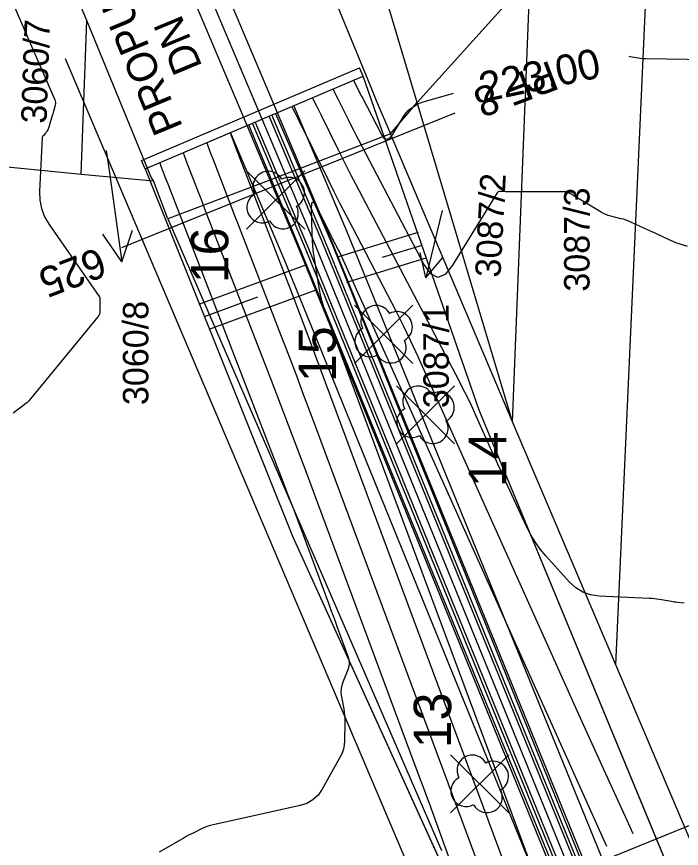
# Model space of a CAD drawing. Extents: x -534410 to -534262, y -1190162 to -1189584.
# Drawn here: x -534356.09 to -534333.9, y -1189974.68 to -1189946.91 of the extents above; entities that cross this region are included whole.
import ezdxf

# ---------------------------------------------------------------- set-up
doc = ezdxf.new("R2010")
doc.units = 0
for name, color, linetype in [('30', 7, 'Continuous'), ('31', 7, 'Continuous'), ('40', 7, 'Continuous'), ('_linie', 7, 'Continuous'), ('_N_osa', 7, 'Continuous'), ('_N_tenká', 7, 'Continuous'), ('_N_tenká_velmi', 7, 'Continuous'), ('_N_text', 7, 'Continuous'), ('_přístup', 7, 'Continuous'), ('_tenka', 7, 'Continuous'), ('_tenká_čárkovaná', 7, 'Continuous'), ('_velmi_tenka', 7, 'Continuous'), ('Default', 7, 'Continuous'), ('Hranice parcel', 7, 'Continuous'), ('Parcelní čísla', 7, 'Continuous'), ('Pop  PČ popisy', 7, 'Continuous'), ('Vnitřní kresba', 7, 'Continuous')]:
    doc.layers.add(name, color=color, linetype=linetype)

msp = doc.modelspace()

# ---------------------------------------------------------------- linework, layer by layer
at = {"layer": '30'}
for points in [[(-534332.347, -1189948.361), (-534335.078, -1189948.316), (-534335.145, -1189948.314), (-534335.212, -1189948.309), (-534335.279, -1189948.301), (-534335.345, -1189948.291), (-534335.61, -1189948.245), (-534335.641, -1189948.24)], [(-534341.513, -1189949.473), (-534342.557, -1189949.771), (-534342.618, -1189949.791), (-534342.676, -1189949.816), (-534342.731, -1189949.846), (-534342.785, -1189949.88), (-534342.994, -1189950.027), (-534343.044, -1189950.066), (-534343.09, -1189950.11), (-534343.13, -1189950.158), (-534343.166, -1189950.21), (-534343.579, -1189950.88), (-534343.658, -1189950.977), (-534343.735, -1189951.007), (-534343.809, -1189950.971), (-534343.881, -1189950.87), (-534344.566, -1189949.564), (-534344.594, -1189949.511), (-534344.622, -1189949.457), (-534344.649, -1189949.403), (-534344.676, -1189949.349), (-534344.783, -1189949.133), (-534344.81, -1189949.079), (-534344.837, -1189949.025), (-534344.837, -1189949.025)], [(-534333.806, -1189966.483), (-534334.037, -1189966.462), (-534334.086, -1189966.456), (-534334.135, -1189966.45), (-534334.184, -1189966.443), (-534334.232, -1189966.436), (-534334.633, -1189966.367), (-534334.717, -1189966.354), (-534334.8, -1189966.343), (-534334.884, -1189966.336), (-534334.968, -1189966.33), (-534336.643, -1189966.251), (-534336.926, -1189966.212), (-534337.185, -1189966.121), (-534337.42, -1189965.978), (-534337.63, -1189965.784), (-534338.423, -1189964.906), (-534338.612, -1189964.681), (-534338.782, -1189964.443), (-534338.934, -1189964.193), (-534339.067, -1189963.93), (-534339.767, -1189962.411), (-534339.896, -1189962.131), (-534340.023, -1189961.852), (-534340.15, -1189961.572), (-534340.277, -1189961.292), (-534340.781, -1189960.17), (-534340.909, -1189959.891), (-534341.041, -1189959.614), (-534341.178, -1189959.338), (-534341.318, -1189959.065), (-534344.768, -1189952.496), (-534344.917, -1189952.21), (-534345.064, -1189951.923), (-534345.21, -1189951.635), (-534345.354, -1189951.346), (-534345.926, -1189950.189), (-534346.069, -1189949.9), (-534346.214, -1189949.612), (-534346.214, -1189949.611)], [(-534349.741, -1189951.113), (-534349.741, -1189951.114), (-534349.634, -1189951.413), (-534349.521, -1189951.711), (-534349.063, -1189952.897), (-534348.948, -1189953.194), (-534348.834, -1189953.49), (-534348.719, -1189953.787), (-534348.604, -1189954.084), (-534347.276, -1189957.52), (-534347.018, -1189958.192), (-534346.762, -1189958.865), (-534346.507, -1189959.539), (-534346.256, -1189960.213), (-534339.969, -1189977.123)], [(-534351.313, -1189951.783), (-534351.313, -1189951.783), (-534351.287, -1189951.853), (-534351.261, -1189951.924), (-534351.125, -1189952.275), (-534351.044, -1189952.485), (-534347.202, -1189962.427), (-534347.031, -1189962.871), (-534346.862, -1189963.316), (-534346.693, -1189963.762), (-534346.527, -1189964.208), (-534345.681, -1189966.484), (-534345.606, -1189966.685), (-534345.532, -1189966.887), (-534345.458, -1189967.088), (-534345.385, -1189967.29), (-534345.025, -1189968.289), (-534344.996, -1189968.395), (-534344.988, -1189968.501), (-534345, -1189968.606), (-534345.033, -1189968.711), (-534345.203, -1189969.129), (-534345.238, -1189969.235), (-534345.257, -1189969.342), (-534345.261, -1189969.45), (-534345.25, -1189969.561), (-534345.171, -1189970.016), (-534345.154, -1189970.129), (-534345.142, -1189970.243), (-534345.136, -1189970.357), (-534345.135, -1189970.472), (-534345.143, -1189971.09), (-534345.154, -1189971.229), (-534345.181, -1189971.363), (-534345.225, -1189971.493), (-534345.285, -1189971.619), (-534345.888, -1189972.697), (-534346.027, -1189972.897), (-534346.197, -1189973.056), (-534346.398, -1189973.173), (-534346.629, -1189973.249), (-534349.578, -1189973.903), (-534349.66, -1189973.924), (-534349.74, -1189973.949), (-534349.818, -1189973.979), (-534349.895, -1189974.014), (-534350.199, -1189974.162), (-534350.275, -1189974.2), (-534350.35, -1189974.239), (-534350.424, -1189974.28), (-534350.497, -1189974.321), (-534351.326, -1189974.802)], [(-534333.937, -1189988.624), (-534345.745, -1189956.862), (-534345.821, -1189956.641), (-534345.887, -1189956.416), (-534345.941, -1189956.189), (-534345.984, -1189955.959), (-534346.144, -1189954.985), (-534346.174, -1189954.777), (-534346.198, -1189954.569), (-534346.214, -1189954.36), (-534346.223, -1189954.15), (-534346.245, -1189953.308), (-534346.238, -1189953.148), (-534346.207, -1189953.088), (-534346.151, -1189953.127), (-534346.07, -1189953.265), (-534345.568, -1189954.282), (-534345.54, -1189954.337), (-534345.513, -1189954.392), (-534345.485, -1189954.446), (-534345.456, -1189954.501), (-534345.342, -1189954.718), (-534345.314, -1189954.773), (-534345.287, -1189954.828), (-534345.26, -1189954.883), (-534345.235, -1189954.939), (-534336.4, -1189974.599)]]:
    msp.add_lwpolyline(points, dxfattribs=at)
at = {"layer": '31'}
for points in [[(-534356.958, -1189944.756), (-534354.814, -1189949.683), (-534354.799, -1189949.726), (-534354.792, -1189949.769), (-534354.792, -1189949.813), (-534354.8, -1189949.858), (-534354.858, -1189950.072), (-534354.865, -1189950.099), (-534354.873, -1189950.126), (-534354.881, -1189950.153), (-534354.889, -1189950.18), (-534354.922, -1189950.287), (-534354.931, -1189950.314), (-534354.939, -1189950.341), (-534354.947, -1189950.368), (-534354.954, -1189950.395), (-534355.012, -1189950.595), (-534355.018, -1189950.613), (-534355.024, -1189950.631), (-534355.032, -1189950.648), (-534355.041, -1189950.665), (-534355.078, -1189950.732), (-534355.088, -1189950.748), (-534355.099, -1189950.763), (-534355.11, -1189950.778), (-534355.123, -1189950.793), (-534355.197, -1189950.871), (-534355.211, -1189950.889), (-534355.222, -1189950.91), (-534355.229, -1189950.931), (-534355.232, -1189950.955), (-534355.32, -1189952.734), (-534355.312, -1189953.032), (-534355.256, -1189953.316), (-534355.153, -1189953.587), (-534355.002, -1189953.844), (-534353.33, -1189956.253), (-534353.322, -1189956.267), (-534353.316, -1189956.281), (-534353.312, -1189956.297), (-534353.311, -1189956.313), (-534353.311, -1189956.736), (-534353.315, -1189956.789), (-534353.328, -1189956.838), (-534353.35, -1189956.885), (-534353.38, -1189956.928), (-534355.625, -1189959.662), (-534355.686, -1189959.732), (-534355.751, -1189959.797), (-534355.821, -1189959.858), (-534355.894, -1189959.915), (-534356.21, -1189960.143)], [(-534333.691, -1189954.585), (-534334.001, -1189954.482), (-534334.079, -1189954.455), (-534334.155, -1189954.426), (-534334.23, -1189954.394), (-534334.305, -1189954.361), (-534334.755, -1189954.146), (-534334.854, -1189954.1), (-534334.952, -1189954.054), (-534335.051, -1189954.008), (-534335.15, -1189953.963), (-534335.583, -1189953.764), (-534335.664, -1189953.73), (-534335.746, -1189953.699), (-534335.83, -1189953.673), (-534335.915, -1189953.651), (-534336.257, -1189953.57), (-534336.342, -1189953.547), (-534336.424, -1189953.517), (-534336.503, -1189953.481), (-534336.579, -1189953.438), (-534337.516, -1189952.864), (-534337.531, -1189952.854), (-534337.547, -1189952.845), (-534337.563, -1189952.836), (-534337.579, -1189952.828), (-534337.661, -1189952.787), (-534337.669, -1189952.782), (-534337.677, -1189952.779), (-534337.685, -1189952.775), (-534337.693, -1189952.771), (-534337.727, -1189952.756), (-534337.735, -1189952.753), (-534337.743, -1189952.751), (-534337.752, -1189952.75), (-534337.761, -1189952.75), (-534337.813, -1189952.751), (-534337.824, -1189952.751), (-534337.836, -1189952.752), (-534337.847, -1189952.752), (-534337.859, -1189952.752), (-534339.627, -1189952.752), (-534339.639, -1189952.752), (-534339.65, -1189952.752), (-534339.662, -1189952.752), (-534339.674, -1189952.753), (-534339.72, -1189952.754), (-534339.732, -1189952.754), (-534339.743, -1189952.754), (-534339.755, -1189952.754), (-534339.766, -1189952.753), (-534339.943, -1189952.739), (-534339.975, -1189952.74), (-534340.002, -1189952.749), (-534340.026, -1189952.766), (-534340.045, -1189952.791), (-534341.534, -1189955.206), (-534341.784, -1189955.513), (-534342.027, -1189955.61), (-534342.263, -1189955.496), (-534342.492, -1189955.173), (-534344.667, -1189951.03), (-534344.756, -1189950.86), (-534344.843, -1189950.69), (-534344.929, -1189950.519), (-534345.015, -1189950.348), (-534345.354, -1189949.661), (-534345.44, -1189949.489), (-534345.525, -1189949.318), (-534345.525, -1189949.318)], [(-534335.502, -1189974.194), (-534335.706, -1189973.75), (-534336.543, -1189971.917), (-534337.375, -1189970.082), (-534338.203, -1189968.246), (-534342.689, -1189958.264), (-534342.928, -1189957.743), (-534343.175, -1189957.226), (-534343.429, -1189956.713), (-534343.692, -1189956.203), (-534344.869, -1189953.962), (-534345.078, -1189953.56), (-534345.286, -1189953.156), (-534345.49, -1189952.751), (-534345.693, -1189952.345), (-534346.692, -1189950.323), (-534346.796, -1189950.113), (-534346.901, -1189949.904), (-534346.901, -1189949.904)], [(-534348.961, -1189950.781), (-534348.961, -1189950.781), (-534348.873, -1189951.024), (-534348.782, -1189951.265), (-534347.95, -1189953.419), (-534347.826, -1189953.741), (-534347.702, -1189954.063), (-534347.577, -1189954.385), (-534347.453, -1189954.707), (-534346.955, -1189955.994), (-534346.832, -1189956.316), (-534346.709, -1189956.639), (-534346.587, -1189956.961), (-534346.466, -1189957.285), (-534337.113, -1189982.443)], [(-534350.527, -1189951.448), (-534350.527, -1189951.448), (-534350.46, -1189951.633), (-534350.391, -1189951.817), (-534350.108, -1189952.551), (-534350.037, -1189952.734), (-534349.966, -1189952.918), (-534349.895, -1189953.101), (-534349.824, -1189953.285), (-534347.597, -1189959.046), (-534347.204, -1189960.069), (-534346.815, -1189961.092), (-534346.428, -1189962.116), (-534346.045, -1189963.142), (-534342.825, -1189971.804), (-534342.573, -1189972.484), (-534342.322, -1189973.165), (-534342.073, -1189973.847), (-534341.826, -1189974.529), (-534340.607, -1189977.906)]]:
    msp.add_lwpolyline(points, dxfattribs=at)
at = {"layer": '_linie'}
for points in [[(-534351.8, -1189951.99), (-534344.52, -1189948.89)], [(-534351.8, -1189951.99), (-534346.88, -1189964.25), (-534328.11, -1190005.55), (-534325.796, -1190021.686), (-534325.86, -1190050.97), (-534326.22, -1190078.56), (-534326.79, -1190120.4), (-534329.12, -1190134.93), (-534323.49, -1190133.89), (-534321.38, -1190121.46), (-534319.59, -1190053.22), (-534320.45, -1190021.195), (-534322.75, -1190003.33), (-534340.65, -1189960.04), (-534344.52, -1189948.89)], [(-534347.45, -1189950.137), (-534345.54, -1189954.54), (-534325.02, -1190005.35), (-534322.054, -1190021.393), (-534321.72, -1190051.56), (-534322.31, -1190078.15), (-534323.81, -1190120.37), (-534326.521, -1190134.45)], [(-534328.194, -1190134.759), (-534324.85, -1190120.45), (-534324.6, -1190078.17), (-534323.54, -1190051.92), (-534323.273, -1190021.516), (-534325.81, -1190005.43), (-534346.66, -1189954.59), (-534348.342, -1189950.518)]]:
    msp.add_lwpolyline(points, dxfattribs=at)
at = {"layer": '_N_osa'}
for points in [[(-534347.892, -1189950.326), (-534351.93, -1189940.77), (-534351.95, -1189940.722)], [(-534327.357, -1190134.604), (-534324.33, -1190120.41), (-534323.455, -1190078.16), (-534322.63, -1190051.74), (-534322.663, -1190021.455), (-534325.415, -1190005.39), (-534346.1, -1189954.565), (-534347.892, -1189950.326)]]:
    msp.add_lwpolyline(points, dxfattribs=at)
at = {"layer": '_N_tenká'}
for points in [[(-534326.133, -1190134.378), (-534323.183, -1190120.543), (-534322.305, -1190078.19), (-534321.48, -1190051.757), (-534321.513, -1190021.356), (-534324.303, -1190005.072), (-534345.038, -1189954.124), (-534346.832, -1189949.878)], [(-534328.581, -1190134.83), (-534325.477, -1190120.277), (-534324.605, -1190078.13), (-534323.78, -1190051.723), (-534323.813, -1190021.553), (-534326.527, -1190005.708), (-534347.162, -1189955.006), (-534348.951, -1189950.773)]]:
    msp.add_lwpolyline(points, dxfattribs=at)
at = {"layer": '_N_tenká_velmi'}
for points in [[(-534326.772, -1190134.496), (-534323.781, -1190120.474), (-534322.905, -1190078.174), (-534322.08, -1190051.748), (-534322.113, -1190021.407), (-534324.883, -1190005.238), (-534345.592, -1189954.354), (-534347.385, -1189950.112)], [(-534327.623, -1190134.654), (-534324.579, -1190120.381), (-534323.705, -1190078.154), (-534322.88, -1190051.736), (-534322.913, -1190021.476), (-534325.657, -1190005.459), (-534346.331, -1189954.661), (-534348.122, -1189950.423)], [(-534327.091, -1190134.555), (-534324.081, -1190120.439), (-534323.205, -1190078.166), (-534322.38, -1190051.744), (-534322.413, -1190021.433), (-534325.173, -1190005.321), (-534345.869, -1189954.469), (-534347.661, -1189950.228)], [(-534326.985, -1190134.536), (-534323.981, -1190120.45), (-534323.105, -1190078.169), (-534322.28, -1190051.745), (-534322.313, -1190021.425), (-534325.076, -1190005.293), (-534345.777, -1189954.431), (-534347.569, -1189950.189)], [(-534327.943, -1190134.713), (-534324.879, -1190120.346), (-534324.005, -1190078.146), (-534323.18, -1190051.732), (-534323.213, -1190021.502), (-534325.947, -1190005.542), (-534346.608, -1189954.776), (-534348.398, -1189950.54)], [(-534327.73, -1190134.673), (-534324.679, -1190120.37), (-534323.805, -1190078.151), (-534322.98, -1190051.735), (-534323.013, -1190021.485), (-534325.754, -1190005.487), (-534346.423, -1189954.699), (-534348.214, -1189950.462)]]:
    msp.add_lwpolyline(points, dxfattribs=at)
at = {"layer": '_N_text'}
for points in [[(-534341.462, -1189950.129), (-534352.588, -1189954.625)], [(-534332.014, -1189973.259), (-534343.129, -1189977.783)]]:
    msp.add_lwpolyline(points, dxfattribs=at)
at = {"layer": '_přístup'}
for p, q in [((-534346.467, -1189954.003), (-534348.413, -1189952.057)), ((-534348.413, -1189954.003), (-534346.467, -1189952.057)), ((-534342.867, -1189958.483), (-534344.813, -1189956.537)), ((-534344.813, -1189958.483), (-534342.867, -1189956.537)), ((-534341.467, -1189961.173), (-534343.413, -1189959.227)), ((-534343.413, -1189961.173), (-534341.467, -1189959.227)), ((-534339.658, -1189973.494), (-534341.604, -1189971.548)), ((-534341.604, -1189973.494), (-534339.658, -1189971.548))]:
    msp.add_line(p, q, dxfattribs=at)
msp.add_lwpolyline([(-534330.552, -1190135.191), (-534328.648, -1190119.819), (-534326.845, -1190024.247), (-534332.805, -1189999.297), (-534354.454, -1189948.317)], dxfattribs=at)
for centre in [(-534347.44, -1189953.03), (-534343.84, -1189957.51), (-534342.44, -1189960.2), (-534340.631, -1189972.521)]:
    msp.add_circle(centre, 0.000512, dxfattribs=at)
for centre, start, end in [((-534347.685, -1189952.581), 28.6209, 208.6209), ((-534346.991, -1189952.785), 298.6209, 118.6209), ((-534347.889, -1189953.275), 118.6209, 298.6209), ((-534347.195, -1189953.479), 208.6209, 28.6209), ((-534344.085, -1189957.061), 28.6209, 208.6209), ((-534343.391, -1189957.265), 298.6209, 118.6209), ((-534344.289, -1189957.755), 118.6209, 298.6209), ((-534343.595, -1189957.959), 208.6209, 28.6209), ((-534342.685, -1189959.751), 28.6209, 208.6209), ((-534341.991, -1189959.955), 298.6209, 118.6209), ((-534342.889, -1189960.445), 118.6209, 298.6209), ((-534342.195, -1189960.649), 208.6209, 28.6209), ((-534340.876, -1189972.072), 28.6209, 208.6209), ((-534340.182, -1189972.276), 298.6209, 118.6209), ((-534341.081, -1189972.766), 118.6209, 298.6209), ((-534340.386, -1189972.971), 208.6209, 28.6209)]:
    msp.add_arc(centre, 0.512, start, end, dxfattribs=at)
at = {"layer": '_tenka'}
for points in [[(-534351.8, -1189951.99), (-534344.52, -1189948.89)], [(-534351.8, -1189951.99), (-534344.52, -1189948.89)], [(-534351.8, -1189951.99), (-534346.88, -1189964.25), (-534328.11, -1190005.55), (-534325.796, -1190021.686), (-534325.86, -1190050.97), (-534326.22, -1190078.56), (-534326.79, -1190120.4), (-534329.12, -1190134.93), (-534323.49, -1190133.89), (-534321.38, -1190121.46), (-534319.59, -1190053.22), (-534320.45, -1190021.195), (-534322.75, -1190003.33), (-534340.65, -1189960.04), (-534344.52, -1189948.89)], [(-534351.8, -1189951.99), (-534344.52, -1189948.89)], [(-534327.55, -1190134.64), (-534323.49, -1190133.89), (-534321.38, -1190121.46), (-534319.59, -1190053.22), (-534320.45, -1190021.195), (-534322.75, -1190003.33), (-534340.65, -1189960.04), (-534344.52, -1189948.89)], [(-534347.45, -1189950.137), (-534345.54, -1189954.54), (-534325.02, -1190005.35), (-534322.054, -1190021.393), (-534321.72, -1190051.56), (-534322.31, -1190078.15), (-534323.81, -1190120.37), (-534326.521, -1190134.45)], [(-534347.45, -1189950.137), (-534345.54, -1189954.54), (-534325.02, -1190005.35), (-534322.054, -1190021.393), (-534321.72, -1190051.56), (-534322.31, -1190078.15), (-534323.81, -1190120.37), (-534326.521, -1190134.45)], [(-534328.194, -1190134.759), (-534324.85, -1190120.45), (-534324.6, -1190078.17), (-534323.54, -1190051.92), (-534323.273, -1190021.516), (-534325.81, -1190005.43), (-534346.66, -1189954.59), (-534348.342, -1189950.518)], [(-534328.194, -1190134.759), (-534324.85, -1190120.45), (-534324.6, -1190078.17), (-534323.54, -1190051.92), (-534323.273, -1190021.516), (-534325.81, -1190005.43), (-534346.66, -1189954.59), (-534348.342, -1189950.518)], [(-534351.8, -1189951.99), (-534346.88, -1189964.25), (-534328.11, -1190005.55), (-534325.796, -1190021.686), (-534325.86, -1190050.97), (-534326.22, -1190078.56), (-534326.79, -1190120.4), (-534329.12, -1190134.93), (-534327.55, -1190134.64)]]:
    msp.add_lwpolyline(points, dxfattribs=at)
at = {"layer": '_tenká_čárkovaná'}
for points in [[(-534347.385, -1189950.112), (-534351.423, -1189940.558), (-534351.442, -1189940.511)], [(-534348.398, -1189950.54), (-534352.437, -1189940.982), (-534352.458, -1189940.932)]]:
    msp.add_lwpolyline(points, dxfattribs=at)
at = {"layer": '_velmi_tenka'}
for p, q in [((-534342.69, -1189954.112), (-534345.342, -1189954.926)), ((-534342.558, -1189954.542), (-534343.884, -1189954.949)), ((-534342.426, -1189954.972), (-534345.078, -1189955.787)), ((-534349.977, -1189956.496), (-534346.397, -1189955.186)), ((-534349.822, -1189956.919), (-534348.032, -1189956.264)), ((-534349.667, -1189957.341), (-534346.087, -1189956.032))]:
    msp.add_line(p, q, dxfattribs=at)
at = {"layer": 'Default'}
for p, q in [((-534340.65, -1189960.04), (-534344.52, -1189948.89)), ((-534344.52, -1189948.89), (-534344.52, -1189948.89)), ((-534351.8, -1189951.99), (-534346.88, -1189964.25)), ((-534322.75, -1190003.33), (-534340.65, -1189960.04)), ((-534346.88, -1189964.25), (-534328.11, -1190005.55))]:
    msp.add_line(p, q, dxfattribs=at)
at = {"layer": 'Hranice parcel'}
for p, q in [((-534342.72, -1189949.77), (-534345.7, -1189939.75)), ((-534353.75, -1189947.04), (-534355.84, -1189941.94)), ((-534339.54, -1189960.43), (-534338.98, -1189946.42)), ((-534336.09, -1189968.55), (-534335.08, -1189946.31)), ((-534353.94, -1189952.16), (-534353.75, -1189947.04)), ((-534351.79, -1189951.81), (-534353.75, -1189947.04)), ((-534343.61, -1189950.82), (-534342.72, -1189949.77)), ((-534339.54, -1189960.43), (-534342.72, -1189949.77)), ((-534339.54, -1189960.43), (-534343.61, -1189950.82)), ((-534356.92, -1189951.87), (-534353.94, -1189952.16)), ((-534353.94, -1189952.16), (-534351.89, -1189952.35)), ((-534351.89, -1189952.35), (-534351.52, -1189952.39)), ((-534351.04, -1189953.66), (-534351.52, -1189952.39)), ((-534351.04, -1189953.66), (-534341.9, -1189974.75)), ((-534336.09, -1189968.55), (-534339.54, -1189960.43)), ((-534333.52, -1189974.6), (-534336.09, -1189968.55))]:
    msp.add_line(p, q, dxfattribs=at)
for points in [[(-534348.85, -1189938.1), (-534348.39, -1189939.21), (-534348.2, -1189939.68), (-534344.29, -1189949.21), (-534344.09, -1189949.7), (-534343.61, -1189950.82)], [(-534342.72, -1189949.77), (-534339.72, -1189946.46), (-534338.98, -1189946.42)], [(-534343.61, -1189950.82), (-534346.53, -1189951.94), (-534347.64, -1189952.36), (-534351.04, -1189953.66)], [(-534351.52, -1189952.39), (-534351.6, -1189952.27), (-534351.79, -1189951.81)]]:
    msp.add_lwpolyline(points, dxfattribs=at)
at = {"layer": 'Pop  PČ popisy'}
for p, q in [((-534353.1, -1189951.37), (-534352.99, -1189952.12)), ((-534352.99, -1189952.12), (-534352.572, -1189955.092)), ((-534341.886, -1189953.381), (-534342.424, -1189955.621)), ((-534352.572, -1189955.092), (-534352.216, -1189954.03)), ((-534352.572, -1189955.092), (-534353.208, -1189954.17)), ((-534342.424, -1189955.621), (-534342.618, -1189954.784)), ((-534342.424, -1189955.621), (-534341.871, -1189954.963))]:
    msp.add_line(p, q, dxfattribs=at)
at = {"layer": 'Vnitřní kresba'}
for p, q in [((-534351.918, -1189951.714), (-534344.638, -1189948.614)), ((-534344.52, -1189948.89), (-534344.638, -1189948.614)), ((-534351.8, -1189951.99), (-534351.918, -1189951.714))]:
    msp.add_line(p, q, dxfattribs=at)

# ---------------------------------------------------------------- texts
at = {"layer": '40'}
msp.add_text('223.00', height=1, rotation=11.9899, dxfattribs=at).set_placement((-534340.532, -1189949.772))
at = {"layer": '_N_text'}
for s, rotation, p in [('PROPUSTEK ', 112.5508, (-534350.53, -1189950.587)), ('DN 1100', 112.5508, (-534349.88, -1189948.571)), ('PF 8', 200.8231, (-534338.277, -1189948.36)), ('625', 200.7755, (-534353.352, -1189954.59))]:
    msp.add_text(s, height=1, rotation=rotation, dxfattribs=at).set_placement(p)
at = {"layer": '_přístup'}
for s, p in [('16', (-534349.022, -1189955.807)), ('15', (-534345.428, -1189959.104)), ('14', (-534339.745, -1189962.619)), ('13', (-534341.583, -1189971.333))]:
    msp.add_text(s, height=1.25, rotation=90, dxfattribs=at).set_placement(p)
at = {"layer": 'Parcelní čísla'}
for s, rotation, p in [('3060/7', 88, (-534355.092, -1189950.487)), ('3087/2', 87, (-534339.937, -1189955.629)), ('3087/3', 90, (-534336.963, -1189956.087)), ('3060/8', 90, (-534351.691, -1189959.874)), ('3087/1', 90, (-534341.661, -1189959.977))]:
    msp.add_text(s, height=0.85, rotation=rotation, dxfattribs=at).set_placement(p)

doc.saveas('drawing.dxf')
